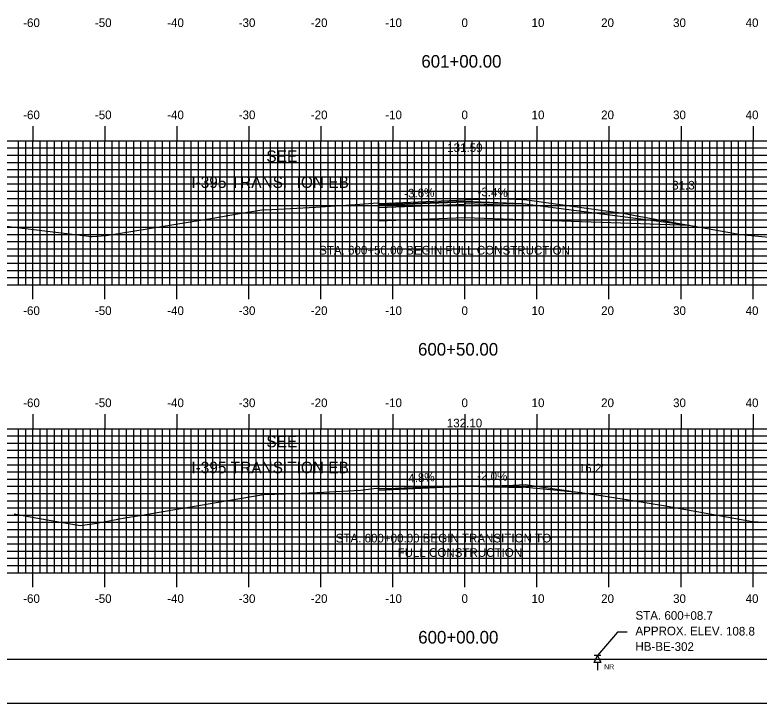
# Model space of a CAD drawing. Extents: x 841388 to 841731, y 363538 to 363758.
# Drawn here: x 841491.4 to 841594.7, y 363537.6 to 363633.2 of the extents above; entities that cross this region are included whole.
import ezdxf

# ---------------------------------------------------------------- set-up
doc = ezdxf.new("R2010")
doc.units = 0
for name, color, linetype in [('ANNOTATION', 7, 'Continuous'), ('BORDER', 7, 'Continuous'), ('BORING - NO REFUSAL', 7, 'Continuous'), ('D_Drainage_Text', 7, 'Continuous'), ('D_Roadway_Centerline', 7, 'Continuous'), ('D_Roadway_Centerline_Text', 7, 'Continuous'), ('D_Roadway_Edge_Shoulder', 7, 'Continuous'), ('D_Roadway_Edge_TW', 7, 'Continuous'), ('D_Roadway_SubGrade', 7, 'Continuous'), ('D_Text_Standard', 7, 'Continuous'), ('H_V ANNOTATION', 7, 'Continuous'), ('M_Roadway_Centerline', 7, 'Continuous'), ('MAJOR', 7, 'Continuous'), ('MINOR', 7, 'Continuous'), ('PLOT BOUNDARY', 7, 'Continuous'), ('S_Roadway_Centerline', 7, 'Continuous')]:
    doc.layers.add(name, color=color, linetype=linetype)

msp = doc.modelspace()

# ---------------------------------------------------------------- linework, layer by layer
at = {"layer": 'ANNOTATION'}
for p, q in [((841541.86, 363606.87), (841541.86, 363604.62)), ((841553.86, 363606.85), (841541.86, 363606.42)), ((841553.86, 363607.31), (841553.86, 363605.06)), ((841553.86, 363607.18), (841553.86, 363606.85)), ((841561.86, 363607.03), (841561.86, 363604.78)), ((841561.86, 363607.03), (841585.05, 363603.98)), ((841561.86, 363604.78), (841585.05, 363603.98)), ((841561.86, 363567.66), (841570.03, 363566.84))]:
    msp.add_line(p, q, dxfattribs=at)
for points in [[(841553.86, 363607.18), (841553.86, 363607.01), (841561.86, 363606.74)], [(841541.86, 363604.62), (841553.86, 363605.06), (841561.86, 363604.78)]]:
    msp.add_lwpolyline(points, dxfattribs=at)
at = {"layer": 'BORDER'}
msp.add_lwpolyline([(841404.26, 363543.72), (841724.26, 363543.72), (841724.26, 363753.72), (841404.26, 363753.72)], close=True, dxfattribs=at)
at = {"layer": 'BORING - NO REFUSAL'}
for p, q in [((841561.86, 363607.03), (841561.86, 363604.78)), ((841572.74, 363544.22), (841571.78, 363544.22)), ((841572.26, 363543.26), (841572.26, 363542.2))]:
    msp.add_line(p, q, dxfattribs=at)
msp.add_lwpolyline([(841576.36, 363547.48), (841575.05, 363547.48), (841572.26, 363544.22)], dxfattribs=at)
msp.add_lwpolyline([(841572.26, 363544.22), (841572.74, 363543.26), (841571.78, 363543.26)], close=True, dxfattribs=at)
at = {"layer": 'D_Roadway_Centerline'}
for points in [[(841541.86, 363606.87), (841553.86, 363607.31), (841561.86, 363607.03)], [(841541.86, 363567.25), (841553.86, 363567.82), (841561.86, 363567.66)]]:
    msp.add_lwpolyline(points, dxfattribs=at)
at = {"layer": 'D_Roadway_Edge_Shoulder'}
for points in [[(841553.86, 363607.31), (841561.86, 363607.03), (841561.86, 363606.91), (841553.86, 363607.18)], [(841553.86, 363567.82), (841561.86, 363567.66), (841561.86, 363567.53), (841553.86, 363567.69)]]:
    msp.add_lwpolyline(points, close=True, dxfattribs=at)
at = {"layer": 'D_Roadway_Edge_TW'}
for points in [[(841541.86, 363606.87), (841553.86, 363607.31), (841553.86, 363607.18), (841541.86, 363606.75)], [(841541.86, 363567.25), (841553.86, 363567.82), (841553.86, 363567.69), (841541.86, 363567.12)]]:
    msp.add_lwpolyline(points, close=True, dxfattribs=at)
for points in [[(841541.86, 363606.87), (841541.86, 363606.75)], [(841541.86, 363567.25), (841541.86, 363567.12)]]:
    msp.add_lwpolyline(points, dxfattribs=at)
at = {"layer": 'D_Roadway_SubGrade'}
for p, q in [((841541.86, 363615.35), (841541.86, 363606.75)), ((841541.86, 363575.72), (841541.86, 363567.12))]:
    msp.add_line(p, q, dxfattribs=at)
at = {"layer": 'MAJOR'}
for p, q in [((841493.86, 363617.73), (841493.86, 363615.72)), ((841503.86, 363617.73), (841503.86, 363615.72)), ((841513.86, 363617.73), (841513.86, 363615.72)), ((841523.86, 363617.73), (841523.86, 363615.72)), ((841533.86, 363617.73), (841533.86, 363615.72)), ((841543.86, 363617.73), (841543.86, 363615.72)), ((841553.86, 363617.73), (841553.86, 363615.72)), ((841563.86, 363617.73), (841563.86, 363615.72)), ((841573.86, 363617.73), (841573.86, 363615.72)), ((841583.86, 363617.73), (841583.86, 363615.72)), ((841593.86, 363617.73), (841593.86, 363615.72)), ((841413.86, 363615.72), (841693.86, 363615.72)), ((841413.86, 363615.72), (841693.86, 363615.72)), ((841493.86, 363595.72), (841493.86, 363615.72)), ((841503.86, 363595.72), (841503.86, 363615.72)), ((841513.86, 363595.72), (841513.86, 363615.72)), ((841523.86, 363595.72), (841523.86, 363615.72)), ((841533.86, 363595.72), (841533.86, 363615.72)), ((841543.86, 363595.72), (841543.86, 363615.72)), ((841553.86, 363595.72), (841553.86, 363615.72)), ((841563.86, 363595.72), (841563.86, 363615.72)), ((841573.86, 363595.72), (841573.86, 363615.72)), ((841583.86, 363595.72), (841583.86, 363615.72)), ((841593.86, 363595.72), (841593.86, 363615.72)), ((841413.86, 363610.72), (841693.86, 363610.72)), ((841413.86, 363605.72), (841693.86, 363605.72)), ((841413.86, 363600.72), (841693.86, 363600.72)), ((841413.86, 363595.72), (841693.86, 363595.72)), ((841413.86, 363595.72), (841693.86, 363595.72)), ((841493.86, 363593.72), (841493.86, 363595.72)), ((841503.86, 363593.72), (841503.86, 363595.72)), ((841513.86, 363593.72), (841513.86, 363595.72)), ((841523.86, 363593.72), (841523.86, 363595.72)), ((841533.86, 363593.72), (841533.86, 363595.72)), ((841543.86, 363593.72), (841543.86, 363595.72)), ((841553.86, 363593.72), (841553.86, 363595.72)), ((841563.86, 363593.72), (841563.86, 363595.72)), ((841573.86, 363593.72), (841573.86, 363595.72)), ((841583.86, 363593.72), (841583.86, 363595.72)), ((841593.86, 363593.72), (841593.86, 363595.72)), ((841493.86, 363577.73), (841493.86, 363575.72)), ((841503.86, 363577.73), (841503.86, 363575.72)), ((841513.86, 363577.73), (841513.86, 363575.72)), ((841523.86, 363577.73), (841523.86, 363575.72)), ((841533.86, 363577.73), (841533.86, 363575.72)), ((841543.86, 363577.73), (841543.86, 363575.72)), ((841553.86, 363577.73), (841553.86, 363575.72)), ((841563.86, 363577.73), (841563.86, 363575.72)), ((841573.86, 363577.73), (841573.86, 363575.72)), ((841583.86, 363577.73), (841583.86, 363575.72)), ((841593.86, 363577.73), (841593.86, 363575.72)), ((841413.86, 363575.72), (841693.86, 363575.72)), ((841413.86, 363575.72), (841693.86, 363575.72)), ((841493.86, 363555.72), (841493.86, 363575.72)), ((841503.86, 363555.72), (841503.86, 363575.72)), ((841513.86, 363555.72), (841513.86, 363575.72)), ((841523.86, 363555.72), (841523.86, 363575.72)), ((841533.86, 363555.72), (841533.86, 363575.72)), ((841543.86, 363555.72), (841543.86, 363575.72)), ((841553.86, 363555.72), (841553.86, 363575.72)), ((841563.86, 363555.72), (841563.86, 363575.72)), ((841573.86, 363555.72), (841573.86, 363575.72)), ((841583.86, 363555.72), (841583.86, 363575.72)), ((841593.86, 363555.72), (841593.86, 363575.72)), ((841413.86, 363570.72), (841693.86, 363570.72)), ((841413.86, 363565.72), (841693.86, 363565.72)), ((841413.86, 363560.72), (841693.86, 363560.72)), ((841413.86, 363555.72), (841693.86, 363555.72)), ((841413.86, 363555.72), (841693.86, 363555.72)), ((841493.86, 363553.72), (841493.86, 363555.72)), ((841503.86, 363553.72), (841503.86, 363555.72)), ((841513.86, 363553.72), (841513.86, 363555.72)), ((841523.86, 363553.72), (841523.86, 363555.72)), ((841533.86, 363553.72), (841533.86, 363555.72)), ((841543.86, 363553.72), (841543.86, 363555.72)), ((841553.86, 363553.72), (841553.86, 363555.72)), ((841563.86, 363553.72), (841563.86, 363555.72)), ((841573.86, 363553.72), (841573.86, 363555.72)), ((841583.86, 363553.72), (841583.86, 363555.72)), ((841593.86, 363553.72), (841593.86, 363555.72))]:
    msp.add_line(p, q, dxfattribs=at)
at = {"layer": 'MINOR'}
for p, q in [((841491.86, 363595.72), (841491.86, 363615.72)), ((841492.86, 363595.72), (841492.86, 363615.72)), ((841494.86, 363595.72), (841494.86, 363615.72)), ((841495.86, 363595.72), (841495.86, 363615.72)), ((841496.86, 363595.72), (841496.86, 363615.72)), ((841497.86, 363595.72), (841497.86, 363615.72)), ((841498.86, 363595.72), (841498.86, 363615.72)), ((841499.86, 363595.72), (841499.86, 363615.72)), ((841500.86, 363595.72), (841500.86, 363615.72)), ((841501.86, 363595.72), (841501.86, 363615.72)), ((841502.86, 363595.72), (841502.86, 363615.72)), ((841504.86, 363595.72), (841504.86, 363615.72)), ((841505.86, 363595.72), (841505.86, 363615.72)), ((841506.86, 363595.72), (841506.86, 363615.72)), ((841507.86, 363595.72), (841507.86, 363615.72)), ((841508.86, 363595.72), (841508.86, 363615.72)), ((841509.86, 363595.72), (841509.86, 363615.72)), ((841510.86, 363595.72), (841510.86, 363615.72)), ((841511.86, 363595.72), (841511.86, 363615.72)), ((841512.86, 363595.72), (841512.86, 363615.72)), ((841514.86, 363595.72), (841514.86, 363615.72)), ((841515.86, 363595.72), (841515.86, 363615.72)), ((841516.86, 363595.72), (841516.86, 363615.72)), ((841517.86, 363595.72), (841517.86, 363615.72)), ((841518.86, 363595.72), (841518.86, 363615.72)), ((841519.86, 363595.72), (841519.86, 363615.72)), ((841520.86, 363595.72), (841520.86, 363615.72)), ((841521.86, 363595.72), (841521.86, 363615.72)), ((841522.86, 363595.72), (841522.86, 363615.72)), ((841524.86, 363595.72), (841524.86, 363615.72)), ((841525.86, 363595.72), (841525.86, 363615.72)), ((841526.86, 363595.72), (841526.86, 363615.72)), ((841527.86, 363595.72), (841527.86, 363615.72)), ((841528.86, 363595.72), (841528.86, 363615.72)), ((841529.86, 363595.72), (841529.86, 363615.72)), ((841530.86, 363595.72), (841530.86, 363615.72)), ((841531.86, 363595.72), (841531.86, 363615.72)), ((841532.86, 363595.72), (841532.86, 363615.72)), ((841534.86, 363595.72), (841534.86, 363615.72)), ((841535.86, 363595.72), (841535.86, 363615.72)), ((841536.86, 363595.72), (841536.86, 363615.72)), ((841537.86, 363595.72), (841537.86, 363615.72)), ((841538.86, 363595.72), (841538.86, 363615.72)), ((841539.86, 363595.72), (841539.86, 363615.72)), ((841540.86, 363595.72), (841540.86, 363615.72)), ((841541.86, 363595.72), (841541.86, 363615.72)), ((841542.86, 363595.72), (841542.86, 363615.72)), ((841544.86, 363595.72), (841544.86, 363615.72)), ((841545.86, 363595.72), (841545.86, 363615.72)), ((841546.86, 363595.72), (841546.86, 363615.72)), ((841547.86, 363595.72), (841547.86, 363615.72)), ((841548.86, 363595.72), (841548.86, 363615.72)), ((841549.86, 363595.72), (841549.86, 363615.72)), ((841550.86, 363595.72), (841550.86, 363615.72)), ((841551.86, 363595.72), (841551.86, 363615.72)), ((841552.86, 363595.72), (841552.86, 363615.72)), ((841554.86, 363595.72), (841554.86, 363615.72)), ((841555.86, 363595.72), (841555.86, 363615.72)), ((841556.86, 363595.72), (841556.86, 363615.72)), ((841557.86, 363595.72), (841557.86, 363615.72)), ((841558.86, 363595.72), (841558.86, 363615.72)), ((841559.86, 363595.72), (841559.86, 363615.72)), ((841560.86, 363595.72), (841560.86, 363615.72)), ((841561.86, 363595.72), (841561.86, 363615.72)), ((841562.86, 363595.72), (841562.86, 363615.72)), ((841564.86, 363595.72), (841564.86, 363615.72)), ((841565.86, 363595.72), (841565.86, 363615.72)), ((841566.86, 363595.72), (841566.86, 363615.72)), ((841567.86, 363595.72), (841567.86, 363615.72)), ((841568.86, 363595.72), (841568.86, 363615.72)), ((841569.86, 363595.72), (841569.86, 363615.72)), ((841570.86, 363595.72), (841570.86, 363615.72)), ((841571.86, 363595.72), (841571.86, 363615.72)), ((841572.86, 363595.72), (841572.86, 363615.72)), ((841574.86, 363595.72), (841574.86, 363615.72)), ((841575.86, 363595.72), (841575.86, 363615.72)), ((841576.86, 363595.72), (841576.86, 363615.72)), ((841577.86, 363595.72), (841577.86, 363615.72)), ((841578.86, 363595.72), (841578.86, 363615.72)), ((841579.86, 363595.72), (841579.86, 363615.72)), ((841580.86, 363595.72), (841580.86, 363615.72)), ((841581.86, 363595.72), (841581.86, 363615.72)), ((841582.86, 363595.72), (841582.86, 363615.72)), ((841584.86, 363595.72), (841584.86, 363615.72)), ((841585.86, 363595.72), (841585.86, 363615.72)), ((841586.86, 363595.72), (841586.86, 363615.72)), ((841587.86, 363595.72), (841587.86, 363615.72)), ((841588.86, 363595.72), (841588.86, 363615.72)), ((841589.86, 363595.72), (841589.86, 363615.72)), ((841590.86, 363595.72), (841590.86, 363615.72)), ((841591.86, 363595.72), (841591.86, 363615.72)), ((841592.86, 363595.72), (841592.86, 363615.72)), ((841413.86, 363614.72), (841693.86, 363614.72)), ((841413.86, 363613.72), (841693.86, 363613.72)), ((841413.86, 363612.72), (841693.86, 363612.72)), ((841413.86, 363611.72), (841693.86, 363611.72)), ((841413.86, 363609.72), (841693.86, 363609.72)), ((841413.86, 363608.72), (841693.86, 363608.72)), ((841413.86, 363607.72), (841693.86, 363607.72)), ((841413.86, 363606.72), (841693.86, 363606.72)), ((841413.86, 363604.72), (841693.86, 363604.72)), ((841413.86, 363603.72), (841693.86, 363603.72)), ((841413.86, 363602.72), (841693.86, 363602.72)), ((841413.86, 363601.72), (841693.86, 363601.72)), ((841413.86, 363599.72), (841693.86, 363599.72)), ((841413.86, 363598.72), (841693.86, 363598.72)), ((841413.86, 363597.72), (841693.86, 363597.72)), ((841413.86, 363596.72), (841693.86, 363596.72)), ((841491.86, 363555.72), (841491.86, 363575.72)), ((841492.86, 363555.72), (841492.86, 363575.72)), ((841494.86, 363555.72), (841494.86, 363575.72)), ((841495.86, 363555.72), (841495.86, 363575.72)), ((841496.86, 363555.72), (841496.86, 363575.72)), ((841497.86, 363555.72), (841497.86, 363575.72)), ((841498.86, 363555.72), (841498.86, 363575.72)), ((841499.86, 363555.72), (841499.86, 363575.72)), ((841500.86, 363555.72), (841500.86, 363575.72)), ((841501.86, 363555.72), (841501.86, 363575.72)), ((841502.86, 363555.72), (841502.86, 363575.72)), ((841504.86, 363555.72), (841504.86, 363575.72)), ((841505.86, 363555.72), (841505.86, 363575.72)), ((841506.86, 363555.72), (841506.86, 363575.72)), ((841507.86, 363555.72), (841507.86, 363575.72)), ((841508.86, 363555.72), (841508.86, 363575.72)), ((841509.86, 363555.72), (841509.86, 363575.72)), ((841510.86, 363555.72), (841510.86, 363575.72)), ((841511.86, 363555.72), (841511.86, 363575.72)), ((841512.86, 363555.72), (841512.86, 363575.72)), ((841514.86, 363555.72), (841514.86, 363575.72)), ((841515.86, 363555.72), (841515.86, 363575.72)), ((841516.86, 363555.72), (841516.86, 363575.72)), ((841517.86, 363555.72), (841517.86, 363575.72)), ((841518.86, 363555.72), (841518.86, 363575.72)), ((841519.86, 363555.72), (841519.86, 363575.72)), ((841520.86, 363555.72), (841520.86, 363575.72)), ((841521.86, 363555.72), (841521.86, 363575.72)), ((841522.86, 363555.72), (841522.86, 363575.72)), ((841524.86, 363555.72), (841524.86, 363575.72)), ((841525.86, 363555.72), (841525.86, 363575.72)), ((841526.86, 363555.72), (841526.86, 363575.72)), ((841527.86, 363555.72), (841527.86, 363575.72)), ((841528.86, 363555.72), (841528.86, 363575.72)), ((841529.86, 363555.72), (841529.86, 363575.72)), ((841530.86, 363555.72), (841530.86, 363575.72)), ((841531.86, 363555.72), (841531.86, 363575.72)), ((841532.86, 363555.72), (841532.86, 363575.72)), ((841534.86, 363555.72), (841534.86, 363575.72)), ((841535.86, 363555.72), (841535.86, 363575.72)), ((841536.86, 363555.72), (841536.86, 363575.72)), ((841537.86, 363555.72), (841537.86, 363575.72)), ((841538.86, 363555.72), (841538.86, 363575.72)), ((841539.86, 363555.72), (841539.86, 363575.72)), ((841540.86, 363555.72), (841540.86, 363575.72)), ((841541.86, 363555.72), (841541.86, 363575.72)), ((841542.86, 363555.72), (841542.86, 363575.72)), ((841544.86, 363555.72), (841544.86, 363575.72)), ((841545.86, 363555.72), (841545.86, 363575.72)), ((841546.86, 363555.72), (841546.86, 363575.72)), ((841547.86, 363555.72), (841547.86, 363575.72)), ((841548.86, 363555.72), (841548.86, 363575.72)), ((841549.86, 363555.72), (841549.86, 363575.72)), ((841550.86, 363555.72), (841550.86, 363575.72)), ((841551.86, 363555.72), (841551.86, 363575.72)), ((841552.86, 363555.72), (841552.86, 363575.72)), ((841554.86, 363555.72), (841554.86, 363575.72)), ((841555.86, 363555.72), (841555.86, 363575.72)), ((841556.86, 363555.72), (841556.86, 363575.72)), ((841557.86, 363555.72), (841557.86, 363575.72)), ((841558.86, 363555.72), (841558.86, 363575.72)), ((841559.86, 363555.72), (841559.86, 363575.72)), ((841560.86, 363555.72), (841560.86, 363575.72)), ((841561.86, 363555.72), (841561.86, 363575.72)), ((841562.86, 363555.72), (841562.86, 363575.72)), ((841564.86, 363555.72), (841564.86, 363575.72)), ((841565.86, 363555.72), (841565.86, 363575.72)), ((841566.86, 363555.72), (841566.86, 363575.72)), ((841567.86, 363555.72), (841567.86, 363575.72)), ((841568.86, 363555.72), (841568.86, 363575.72)), ((841569.86, 363555.72), (841569.86, 363575.72)), ((841570.86, 363555.72), (841570.86, 363575.72)), ((841571.86, 363555.72), (841571.86, 363575.72)), ((841572.86, 363555.72), (841572.86, 363575.72)), ((841574.86, 363555.72), (841574.86, 363575.72)), ((841575.86, 363555.72), (841575.86, 363575.72)), ((841576.86, 363555.72), (841576.86, 363575.72)), ((841577.86, 363555.72), (841577.86, 363575.72)), ((841578.86, 363555.72), (841578.86, 363575.72)), ((841579.86, 363555.72), (841579.86, 363575.72)), ((841580.86, 363555.72), (841580.86, 363575.72)), ((841581.86, 363555.72), (841581.86, 363575.72)), ((841582.86, 363555.72), (841582.86, 363575.72)), ((841584.86, 363555.72), (841584.86, 363575.72)), ((841585.86, 363555.72), (841585.86, 363575.72)), ((841586.86, 363555.72), (841586.86, 363575.72)), ((841587.86, 363555.72), (841587.86, 363575.72)), ((841588.86, 363555.72), (841588.86, 363575.72)), ((841589.86, 363555.72), (841589.86, 363575.72)), ((841590.86, 363555.72), (841590.86, 363575.72)), ((841591.86, 363555.72), (841591.86, 363575.72)), ((841592.86, 363555.72), (841592.86, 363575.72)), ((841413.86, 363574.72), (841693.86, 363574.72)), ((841413.86, 363573.72), (841693.86, 363573.72)), ((841413.86, 363572.72), (841693.86, 363572.72)), ((841413.86, 363571.72), (841693.86, 363571.72)), ((841413.86, 363569.72), (841693.86, 363569.72)), ((841413.86, 363568.72), (841693.86, 363568.72)), ((841413.86, 363567.72), (841693.86, 363567.72)), ((841413.86, 363566.72), (841693.86, 363566.72)), ((841413.86, 363564.72), (841693.86, 363564.72)), ((841413.86, 363563.72), (841693.86, 363563.72)), ((841413.86, 363562.72), (841693.86, 363562.72)), ((841413.86, 363561.72), (841693.86, 363561.72)), ((841413.86, 363559.72), (841693.86, 363559.72)), ((841413.86, 363558.72), (841693.86, 363558.72)), ((841413.86, 363557.72), (841693.86, 363557.72)), ((841413.86, 363556.72), (841693.86, 363556.72))]:
    msp.add_line(p, q, dxfattribs=at)
at = {"layer": 'PLOT BOUNDARY'}
msp.add_lwpolyline([(841388.07, 363537.6), (841728.07, 363537.6), (841728.07, 363757.6), (841388.07, 363757.6)], close=True, dxfattribs=at)
at = {"layer": 'S_Roadway_Centerline'}
for points in [[(841488.96, 363604), (841501.64, 363602.47), (841501.91, 363602.44), (841502.07, 363602.44), (841504.02, 363602.56), (841519.13, 363605.03), (841521.98, 363605.52), (841525.93, 363606.19), (841526.18, 363606.14), (841533.1, 363606.51), (841538.03, 363606.81), (841541.71, 363607.1), (841542.05, 363607.03), (841546.29, 363607.18), (841556.97, 363607.66), (841558.81, 363607.69), (841561.97, 363607.58), (841562.46, 363607.52), (841574.09, 363605.91), (841575.53, 363605.69), (841578.23, 363605.2), (841592.16, 363602.72), (841598.49, 363602.11)], [(841491.28, 363563.9), (841494.77, 363563.26), (841500.44, 363562.26), (841502.74, 363562.62), (841506.62, 363563.33), (841509.05, 363563.72), (841511.38, 363564.12), (841524.77, 363566.42), (841525.9, 363566.58), (841528.92, 363566.68), (841533.35, 363566.84), (841539.33, 363567.2), (841541.57, 363567.44), (841543.01, 363567.4), (841546.62, 363567.55), (841559.03, 363567.85), (841559.66, 363567.84), (841562.2, 363567.96), (841564.74, 363567.62), (841572.45, 363566.49), (841577.18, 363565.74), (841581.44, 363565.07), (841593.81, 363562.85), (841597.04, 363562.63)]]:
    msp.add_lwpolyline(points, dxfattribs=at)

# ---------------------------------------------------------------- texts
at = {"layer": 'ANNOTATION'}
for s, p in [('SEE', (841526.28, 363612.77)), ('I-395 TRANSITION EB', (841515.86, 363609.17)), ('SEE', (841526.28, 363573.14)), ('I-395 TRANSITION EB', (841515.86, 363569.54))]:
    msp.add_text(s, height=1.6, dxfattribs=at).set_placement(p)
for s, rotation, p in [('-3.6%', 2.0618, (841545.44, 363607.8)), ('-3.4%', 358.0323, (841555.59, 363608.05)), ('-4.8%', 2.7252, (841545.48, 363568.22)), ('-2.0%', 358.8542, (841555.54, 363568.59))]:
    msp.add_text(s, height=1.2, rotation=rotation, dxfattribs=at).set_placement(p)
at = {"layer": 'BORING - NO REFUSAL'}
for s, p in [('STA. 600+08.7', (841577.54, 363549.2)), ('APPROX. ELEV. 108.8', (841577.53, 363547.04)), ('HB-BE-302', (841577.53, 363544.88))]:
    msp.add_text(s, height=1.2, rotation=359.8142, dxfattribs=at).set_placement(p)
msp.add_text('NR', height=0.7, dxfattribs=at).set_placement((841573.19, 363542.31))
at = {"layer": 'D_Drainage_Text'}
for s, p in [('STA. 600+50.00 BEGIN FULL CONSTRUCTION', (841533.61, 363599.92)), ('STA. 600+00.00 BEGIN TRANSITION TO', (841535.91, 363559.92)), ('FULL CONSTRUCTION', (841544.5, 363557.92))]:
    msp.add_text(s, height=1.2, dxfattribs=at).set_placement(p)
at = {"layer": 'D_Roadway_Centerline_Text'}
for s, p in [('131.59', (841551.39, 363614.16)), ('132.10', (841551.34, 363575.91))]:
    msp.add_text(s, height=1.2, dxfattribs=at).set_placement(p)
at = {"layer": 'D_Text_Standard'}
for s, p in [("31.3'", (841582.64, 363608.95)), ("16.2'", (841569.67, 363569.64))]:
    msp.add_text(s, height=1.2, dxfattribs=at).set_placement(p)
at = {"layer": 'H_V ANNOTATION'}
for s, height, p in [('-60', 1.2, (841492.51, 363631.52)), ('-50', 1.2, (841502.47, 363631.52)), ('-40', 1.2, (841512.51, 363631.52)), ('-30', 1.2, (841522.44, 363631.52)), ('-20', 1.2, (841532.45, 363631.52)), ('-10', 1.2, (841542.79, 363631.52)), ('0', 1.2, (841553.38, 363631.52)), ('10', 1.2, (841563.11, 363631.52)), ('20', 1.2, (841572.77, 363631.52)), ('30', 1.2, (841582.76, 363631.52)), ('40', 1.2, (841592.83, 363631.52)), ('601+00.00', 1.75, (841547.8, 363625.88)), ('-60', 1.2, (841492.51, 363618.72)), ('-50', 1.2, (841502.47, 363618.72)), ('-40', 1.2, (841512.51, 363618.72)), ('-30', 1.2, (841522.44, 363618.72)), ('-20', 1.2, (841532.45, 363618.72)), ('-10', 1.2, (841542.79, 363618.72)), ('0', 1.2, (841553.38, 363618.72)), ('10', 1.2, (841563.11, 363618.72)), ('20', 1.2, (841572.77, 363618.72)), ('30', 1.2, (841582.76, 363618.72)), ('40', 1.2, (841592.83, 363618.72)), ('-60', 1.2, (841492.51, 363591.52)), ('-50', 1.2, (841502.47, 363591.52)), ('-40', 1.2, (841512.51, 363591.52)), ('-30', 1.2, (841522.44, 363591.52)), ('-20', 1.2, (841532.45, 363591.52)), ('-10', 1.2, (841542.79, 363591.52)), ('0', 1.2, (841553.38, 363591.52)), ('10', 1.2, (841563.11, 363591.52)), ('20', 1.2, (841572.77, 363591.52)), ('30', 1.2, (841582.76, 363591.52)), ('40', 1.2, (841592.83, 363591.52)), ('600+50.00', 1.75, (841547.34, 363585.88)), ('-60', 1.2, (841492.51, 363578.72)), ('-50', 1.2, (841502.47, 363578.72)), ('-40', 1.2, (841512.51, 363578.72)), ('-30', 1.2, (841522.44, 363578.72)), ('-20', 1.2, (841532.45, 363578.72)), ('-10', 1.2, (841542.79, 363578.72)), ('0', 1.2, (841553.38, 363578.72)), ('10', 1.2, (841563.11, 363578.72)), ('20', 1.2, (841572.77, 363578.72)), ('30', 1.2, (841582.76, 363578.72)), ('40', 1.2, (841592.83, 363578.72)), ('-60', 1.2, (841492.51, 363551.52)), ('-50', 1.2, (841502.47, 363551.52)), ('-40', 1.2, (841512.51, 363551.52)), ('-30', 1.2, (841522.44, 363551.52)), ('-20', 1.2, (841532.45, 363551.52)), ('-10', 1.2, (841542.79, 363551.52)), ('0', 1.2, (841553.38, 363551.52)), ('10', 1.2, (841563.11, 363551.52)), ('20', 1.2, (841572.77, 363551.52)), ('30', 1.2, (841582.76, 363551.52)), ('40', 1.2, (841592.83, 363551.52)), ('600+00.00', 1.75, (841547.37, 363545.88))]:
    msp.add_text(s, height=height, dxfattribs=at).set_placement(p)
at = {"layer": 'M_Roadway_Centerline'}
for s, p in [('C', (841541.7, 363607.1)), ('L', (841541.71, 363607.09)), ('C', (841541.56, 363567.44)), ('L', (841541.57, 363567.43))]:
    msp.add_text(s, height=0.0146, dxfattribs=at).set_placement(p)

doc.saveas('drawing.dxf')
